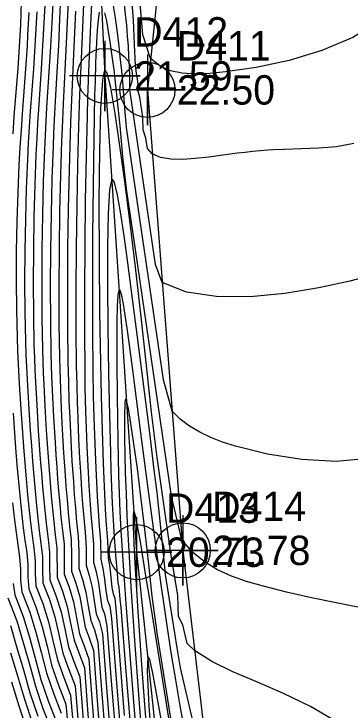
# Model space of a CAD drawing. Extents: x 2356077 to 2359823, y 225951 to 227822.
# Drawn here: x 2356540.3 to 2356568.9, y 227137.3 to 227196.5 of the extents above; entities that cross this region are included whole.
import ezdxf

# ---------------------------------------------------------------- set-up
doc = ezdxf.new("R2010")
doc.units = 0
for name, color, linetype in [('DTM Contours Major', 7, 'Continuous'), ('DTM Contours Minor', 7, 'Continuous'), ('Exist DTM Breakline', 7, 'Continuous'), ('Exist DTM Breakline Cogo Elevation', 7, 'Continuous'), ('Exist DTM Breakline Cogo Number', 7, 'Continuous'), ('Exist DTM Breakline Cogo Point CELL', 7, 'Continuous'), ('Exist DTM Drainline', 7, 'Continuous'), ('Exist DTM Drainline Cogo Elevation', 7, 'Continuous'), ('Exist DTM Drainline Cogo Number', 7, 'Continuous'), ('Exist DTM Drainline Cogo Point CELL', 7, 'Continuous')]:
    doc.layers.add(name, color=color, linetype=linetype)

msp = doc.modelspace()

# ---------------------------------------------------------------- linework, layer by layer
at = {"layer": 'DTM Contours Major'}
for points in [[(2356543.668, 227197.932), (2356543.555, 227195.776), (2356543.435, 227193.728), (2356543.102, 227188.52), (2356543.036, 227187.379), (2356542.973, 227186.181), (2356542.914, 227184.917), (2356542.816, 227182.253), (2356542.744, 227179.401), (2356542.698, 227176.454), (2356542.682, 227173.504), (2356542.698, 227170.646), (2356542.747, 227167.971), (2356542.779, 227166.924), (2356542.815, 227165.921), (2356542.857, 227164.957), (2356542.95, 227163.128), (2356543.071, 227161.068), (2356543.146, 227159.914), (2356543.225, 227158.787), (2356543.308, 227157.677), (2356543.397, 227156.58), (2356543.492, 227155.488), (2356543.594, 227154.39), (2356543.708, 227153.284), (2356543.837, 227152.165), (2356543.983, 227151.026), (2356543.989, 227148.575), (2356544.463, 227147.359), (2356544.86, 227146.052), (2356545.142, 227144.658), (2356545.433, 227143.196), (2356546.314, 227140.837), (2356546.579, 227137.306), (2356546.84, 227133.897)], [(2356546.929, 227197.348), (2356546.867, 227196.192), (2356546.806, 227194.951), (2356546.747, 227193.627), (2356546.662, 227191.54), (2356546.587, 227189.381), (2356546.54, 227187.827), (2356546.456, 227184.368), (2356546.388, 227180.637), (2356546.341, 227176.794), (2356546.315, 227173.003), (2356546.315, 227169.425), (2356546.341, 227166.221), (2356546.368, 227164.716), (2356546.419, 227162.698), (2356546.468, 227161.25), (2356546.531, 227159.692), (2356546.641, 227157.479), (2356546.706, 227156.322), (2356546.781, 227155.144), (2356546.869, 227153.938), (2356546.974, 227152.694), (2356547.097, 227151.397), (2356547.098, 227149.853), (2356547.307, 227149.016), (2356547.506, 227148.06), (2356547.649, 227146.995), (2356547.806, 227146.016), (2356548.034, 227145.43), (2356548.236, 227144.407), (2356548.56, 227140.088), (2356548.898, 227135.954)], [(2356570.489, 227158.651), (2356567.746, 227158.419), (2356564.825, 227158.57), (2356561.905, 227159.027), (2356559.169, 227159.71), (2356558.084, 227160.061), (2356557.07, 227160.452), (2356556.13, 227160.898), (2356555.266, 227161.411), (2356554.483, 227162.005), (2356553.783, 227162.691), (2356553.037, 227165.347), (2356550.876, 227180.208), (2356549.902, 227186.839), (2356549.751, 227188.487), (2356549.61, 227190.39), (2356549.497, 227191.653), (2356549.375, 227192.847), (2356549.243, 227193.998), (2356549.103, 227195.106), (2356548.957, 227196.169), (2356548.807, 227197.187)], [(2356553.962, 227134.786), (2356552.55, 227143.654), (2356552.093, 227146.937), (2356551.768, 227149.936), (2356551.435, 227152.861), (2356551.128, 227155.414), (2356550.825, 227157.797), (2356550.538, 227159.908), (2356550.28, 227161.646), (2356550.064, 227162.91), (2356549.902, 227163.599), (2356549.854, 227163.694), (2356549.816, 227163.686), (2356549.787, 227163.584), (2356549.765, 227163.397), (2356549.75, 227163.136), (2356549.735, 227162.513), (2356549.731, 227161.598), (2356549.74, 227160.407), (2356549.762, 227159.016), (2356549.801, 227157.439), (2356549.859, 227155.689), (2356549.937, 227153.781), (2356550.038, 227151.727), (2356550.147, 227149.8), (2356550.274, 227147.75), (2356550.581, 227143.176), (2356550.941, 227138.188), (2356551.339, 227132.961)], [(2356540.204, 227154.897), (2356540.369, 227153.404), (2356540.498, 227152.361), (2356540.639, 227151.324), (2356540.796, 227150.288), (2356540.87, 227149.255), (2356540.871, 227148.3), (2356540.987, 227147.327), (2356541.665, 227145.585), (2356542.191, 227143.883), (2356542.635, 227142.18), (2356543.086, 227140.417), (2356543.678, 227138.703), (2356544.347, 227136.985)], [(2356540.122, 227139.663), (2356540.749, 227137.606), (2356541.442, 227135.485)]]:
    msp.add_lwpolyline(points, dxfattribs=at)
at = {"layer": 'DTM Contours Minor'}
for points in [[(2356542.763, 227227.301), (2356542.028, 227218.472), (2356541.785, 227215.396), (2356541.559, 227212.326), (2356541.364, 227209.335), (2356541.213, 227206.5), (2356541.143, 227204.817), (2356541.091, 227203.219), (2356541.015, 227200.246), (2356540.981, 227198.855), (2356540.942, 227197.518), (2356540.906, 227196.553), (2356540.865, 227195.607), (2356540.818, 227194.67), (2356540.765, 227193.737), (2356540.706, 227192.799), (2356540.64, 227191.848), (2356540.434, 227189.167), (2356540.324, 227187.761), (2356540.216, 227186.305)], [(2356573.337, 227197.672), (2356571.477, 227195.905), (2356569.154, 227194.485), (2356566.522, 227193.377), (2356563.736, 227192.545), (2356560.95, 227191.952), (2356558.319, 227191.563), (2356556.988, 227191.429), (2356555.757, 227191.38), (2356554.633, 227191.448), (2356553.62, 227191.668), (2356552.726, 227192.072), (2356551.955, 227192.696), (2356551.295, 227194.728), (2356550.372, 227205.324)], [(2356546.386, 227200.636), (2356546.006, 227192.009), (2356545.909, 227189.6), (2356545.819, 227186.945), (2356545.734, 227183.703), (2356545.666, 227180.204), (2356545.618, 227176.592), (2356545.594, 227173.015), (2356545.596, 227169.617), (2356545.628, 227166.545), (2356545.661, 227164.926), (2356545.703, 227163.448), (2356545.752, 227162.086), (2356545.828, 227160.333), (2356545.913, 227158.69), (2356546.008, 227157.09), (2356546.082, 227155.952), (2356546.166, 227154.794), (2356546.263, 227153.608), (2356546.378, 227152.388), (2356546.474, 227151.073), (2356546.475, 227149.593), (2356546.733, 227148.698), (2356546.979, 227147.686), (2356547.147, 227146.55), (2356547.331, 227145.445), (2356547.6, 227144.754), (2356547.849, 227143.733), (2356548.163, 227139.539), (2356548.489, 227135.533)], [(2356544.997, 227198.977), (2356544.89, 227196.395), (2356544.776, 227194.013), (2356544.508, 227188.859), (2356544.414, 227186.807), (2356544.37, 227185.708), (2356544.278, 227182.812), (2356544.207, 227179.685), (2356544.159, 227176.446), (2356544.139, 227173.215), (2356544.148, 227170.109), (2356544.19, 227167.248), (2356544.213, 227166.306), (2356544.27, 227164.545), (2356544.339, 227162.922), (2356544.43, 227161.116), (2356544.547, 227159.141), (2356544.677, 227157.242), (2356544.747, 227156.299), (2356544.837, 227155.184), (2356544.937, 227154.054), (2356545.051, 227152.903), (2356545.184, 227151.726), (2356545.229, 227150.426), (2356545.23, 227149.076), (2356545.594, 227148.039), (2356545.921, 227146.889), (2356546.379, 227144.305), (2356546.732, 227143.4), (2356547.079, 227142.313), (2356547.37, 227138.428), (2356547.667, 227134.706)], [(2356569.24, 227185.465), (2356567.775, 227185.197), (2356566.265, 227185.067), (2356564.756, 227185.008), (2356563.328, 227184.96), (2356562.397, 227184.917), (2356561.937, 227184.889), (2356561.284, 227184.839), (2356560.637, 227184.78), (2356559.995, 227184.712), (2356559.358, 227184.637), (2356558.092, 227184.474), (2356556.899, 227184.314), (2356555.742, 227184.18), (2356554.654, 227184.106), (2356553.663, 227184.126), (2356552.802, 227184.275), (2356552.1, 227184.585), (2356551.675, 227185.038), (2356551.544, 227185.938), (2356551.313, 227186.636), (2356551.283, 227187.71), (2356551.032, 227189.427), (2356550.915, 227189.822), (2356550.859, 227189.988), (2356550.786, 227190.181), (2356550.896, 227190.515), (2356550.847, 227190.953), (2356550.753, 227191.468), (2356550.662, 227192.095), (2356550.621, 227193.302), (2356550.595, 227193.938), (2356550.485, 227195.977), (2356550.329, 227198.168)], [(2356542.978, 227197.74), (2356542.878, 227195.731), (2356542.765, 227193.776), (2356542.637, 227191.791), (2356542.408, 227188.405), (2356542.332, 227187.18), (2356542.26, 227185.896), (2356542.193, 227184.544), (2356542.093, 227181.969), (2356542.019, 227179.236), (2356541.973, 227176.426), (2356541.958, 227173.616), (2356541.975, 227170.885), (2356542.027, 227168.312), (2356542.062, 227167.22), (2356542.103, 227166.172), (2356542.15, 227165.162), (2356542.255, 227163.237), (2356542.392, 227161.05), (2356542.476, 227159.819), (2356542.564, 227158.612), (2356542.657, 227157.423), (2356542.757, 227156.247), (2356542.865, 227155.078), (2356542.973, 227153.989), (2356543.093, 227152.896), (2356543.229, 227151.793), (2356543.36, 227150.664), (2356543.361, 227149.488), (2356543.387, 227148.331), (2356543.9, 227147.014), (2356544.328, 227145.625), (2356544.641, 227144.17), (2356544.962, 227142.646), (2356545.428, 227141.374), (2356545.931, 227140.083), (2356546.426, 227133.498)], [(2356544.262, 227197.316), (2356544.211, 227196.086), (2356544.101, 227193.782), (2356543.98, 227191.563), (2356543.809, 227188.564), (2356543.698, 227186.38), (2356543.647, 227185.204), (2356543.552, 227182.448), (2356543.479, 227179.48), (2356543.432, 227176.406), (2356543.413, 227173.331), (2356543.425, 227170.361), (2356543.47, 227167.601), (2356543.497, 227166.607), (2356543.529, 227165.657), (2356543.603, 227163.868), (2356543.688, 227162.201), (2356543.817, 227160.016), (2356543.886, 227158.966), (2356543.959, 227157.936), (2356544.036, 227156.916), (2356544.119, 227155.898), (2356544.215, 227154.792), (2356544.322, 227153.674), (2356544.444, 227152.539), (2356544.585, 227151.381), (2356544.606, 227150.109), (2356544.607, 227148.823), (2356545.028, 227147.702), (2356545.391, 227146.474), (2356545.904, 227143.743), (2356546.298, 227142.724), (2356546.696, 227141.58), (2356546.974, 227137.868), (2356547.255, 227134.299)], [(2356569.882, 227174.016), (2356568.916, 227173.762), (2356566.283, 227173.181), (2356563.386, 227172.71), (2356560.415, 227172.434), (2356557.557, 227172.439), (2356555.003, 227172.812), (2356552.941, 227173.638), (2356552.36, 227175.167), (2356551.068, 227184.039), (2356550.24, 227189.68), (2356550.212, 227189.848), (2356550.184, 227190.055), (2356550.174, 227191.151), (2356550.152, 227192.016), (2356550.114, 227192.884), (2356550.061, 227193.759), (2356549.996, 227194.647), (2356549.917, 227195.551), (2356549.826, 227196.477), (2356549.673, 227197.875)], [(2356541.581, 227196.628), (2356541.537, 227195.664), (2356541.487, 227194.711), (2356541.432, 227193.761), (2356541.305, 227191.838), (2356541.019, 227187.984), (2356540.922, 227186.603), (2356540.829, 227185.165), (2356540.745, 227183.664), (2356540.641, 227181.294), (2356540.566, 227178.822), (2356540.521, 227176.3), (2356540.508, 227173.783), (2356540.528, 227171.322), (2356540.582, 227168.972), (2356540.625, 227167.806), (2356540.676, 227166.679), (2356540.734, 227165.586), (2356540.797, 227164.521), (2356540.933, 227162.451), (2356541.134, 227159.648), (2356541.241, 227158.275), (2356541.356, 227156.919), (2356541.48, 227155.578), (2356541.615, 227154.25), (2356541.734, 227153.181), (2356541.865, 227152.114), (2356542.012, 227151.043), (2356542.115, 227149.952), (2356542.116, 227148.887), (2356542.184, 227147.835), (2356542.779, 227146.31), (2356543.261, 227144.759), (2356543.638, 227143.181), (2356544.023, 227141.536), (2356544.555, 227140.033), (2356545.142, 227138.527), (2356545.392, 227135.607)], [(2356542.255, 227196.685), (2356542.207, 227195.706), (2356542.099, 227193.776), (2356541.971, 227191.821), (2356541.714, 227188.2), (2356541.627, 227186.897), (2356541.545, 227185.534), (2356541.47, 227184.104), (2356541.367, 227181.631), (2356541.292, 227179.029), (2356541.247, 227176.363), (2356541.233, 227173.7), (2356541.251, 227171.105), (2356541.305, 227168.643), (2356541.344, 227167.512), (2356541.39, 227166.423), (2356541.442, 227165.371), (2356541.559, 227163.353), (2356541.712, 227161.042), (2356541.805, 227159.731), (2356541.903, 227158.443), (2356542.007, 227157.171), (2356542.118, 227155.914), (2356542.239, 227154.666), (2356542.353, 227153.587), (2356542.479, 227152.506), (2356542.621, 227151.419), (2356542.738, 227150.306), (2356542.738, 227149.185), (2356542.785, 227148.085), (2356543.338, 227146.664), (2356543.795, 227145.194), (2356544.139, 227143.677), (2356544.493, 227142.092), (2356544.992, 227140.702), (2356545.537, 227139.304), (2356545.787, 227136.175)], [(2356545.549, 227196.719), (2356545.388, 227193.065), (2356545.212, 227189.2), (2356545.136, 227187.293), (2356545.1, 227186.277), (2356545.011, 227183.222), (2356544.941, 227179.921), (2356544.893, 227176.505), (2356544.87, 227173.107), (2356544.875, 227169.86), (2356544.911, 227166.896), (2356544.952, 227165.162), (2356545.004, 227163.577), (2356545.065, 227162.114), (2356545.158, 227160.221), (2356545.261, 227158.438), (2356545.377, 227156.696), (2356545.459, 227155.571), (2356545.551, 227154.428), (2356545.657, 227153.261), (2356545.781, 227152.063), (2356545.851, 227150.748), (2356545.852, 227149.333), (2356546.162, 227148.372), (2356546.45, 227147.294), (2356546.646, 227146.09), (2356546.855, 227144.875), (2356547.166, 227144.077), (2356547.463, 227143.033), (2356547.766, 227138.985), (2356548.079, 227135.117)], [(2356547.569, 227196.652), (2356547.485, 227195.995), (2356547.412, 227195.119), (2356547.349, 227194.052), (2356547.274, 227192.324), (2356547.222, 227190.728), (2356547.191, 227189.575), (2356547.113, 227185.895), (2356547.055, 227181.853), (2356547.018, 227177.651), (2356547.003, 227173.488), (2356547.01, 227169.565), (2356547.042, 227166.082), (2356547.077, 227163.983), (2356547.122, 227162.144), (2356547.194, 227159.896), (2356547.277, 227157.848), (2356547.334, 227156.65), (2356547.399, 227155.441), (2356547.477, 227154.208), (2356547.571, 227152.937), (2356547.685, 227151.618), (2356547.72, 227150.085), (2356547.893, 227149.302), (2356548.035, 227148.387), (2356548.153, 227147.402), (2356548.283, 227146.584), (2356548.47, 227146.103), (2356548.627, 227145.035), (2356548.957, 227140.627), (2356549.306, 227136.379)], [(2356571.57, 227145.602), (2356567.735, 227146.367), (2356565.641, 227146.807), (2356563.522, 227147.289), (2356561.446, 227147.816), (2356560.114, 227148.202), (2356558.843, 227148.647), (2356557.647, 227149.187), (2356556.538, 227149.859), (2356555.526, 227150.7), (2356554.624, 227151.747), (2356553.724, 227155.47), (2356550.673, 227176.446), (2356549.914, 227181.614), (2356549.589, 227184.375), (2356549.356, 227186.963), (2356549.115, 227189.35), (2356548.842, 227191.727), (2356548.717, 227192.706), (2356548.547, 227193.93), (2356548.378, 227195.01), (2356548.214, 227195.912), (2356548.057, 227196.602)], [(2356567.834, 227136.218), (2356565.576, 227137.551), (2356563.278, 227138.665), (2356561.04, 227139.629), (2356558.964, 227140.512), (2356557.151, 227141.385), (2356555.702, 227142.316), (2356555.069, 227142.92), (2356554.703, 227144.513), (2356554.322, 227145.221), (2356554.288, 227146.102), (2356554.261, 227146.992), (2356553.684, 227150.616), (2356552.501, 227158.737), (2356552.018, 227162.597), (2356551.597, 227166.583), (2356551.14, 227170.724), (2356550.656, 227174.942), (2356550.213, 227178.681), (2356549.77, 227182.248), (2356549.347, 227185.271), (2356548.941, 227188.03), (2356548.575, 227190.228), (2356548.265, 227191.415), (2356548.223, 227191.51), (2356548.183, 227191.581), (2356548.145, 227191.627), (2356548.108, 227191.648), (2356548.072, 227191.644), (2356548.038, 227191.614), (2356548.005, 227191.554), (2356547.973, 227191.466), (2356547.943, 227191.351), (2356547.914, 227191.208), (2356547.886, 227191.04), (2356547.86, 227190.846), (2356547.693, 227188.462), (2356547.597, 227184.892), (2356547.56, 227180.538), (2356547.569, 227175.808), (2356547.613, 227171.104), (2356547.68, 227166.831), (2356547.743, 227163.936), (2356547.822, 227161.063), (2356547.915, 227158.267), (2356547.967, 227156.927), (2356548.025, 227155.62), (2356548.093, 227154.322), (2356548.175, 227153.009), (2356548.277, 227151.659), (2356548.343, 227150.181), (2356548.482, 227149.427), (2356548.663, 227147.686), (2356548.763, 227147.143), (2356548.909, 227146.767), (2356549.026, 227145.558), (2356549.358, 227141.119), (2356549.714, 227136.785)], [(2356556.022, 227134.262), (2356554.51, 227140.858), (2356554.22, 227142.558), (2356553.226, 227148.799), (2356553.094, 227149.999), (2356552.908, 227151.956), (2356552.711, 227153.862), (2356552.498, 227155.772), (2356552.268, 227157.706), (2356551.875, 227160.844), (2356550.833, 227168.997), (2356550.325, 227172.911), (2356550.006, 227175.319), (2356549.689, 227177.617), (2356549.383, 227179.643), (2356549.099, 227181.233), (2356548.849, 227182.225), (2356548.642, 227182.456), (2356548.458, 227181.539), (2356548.345, 227179.507), (2356548.292, 227176.673), (2356548.286, 227173.355), (2356548.314, 227169.866), (2356548.375, 227165.904), (2356548.452, 227162.357), (2356548.536, 227159.15), (2356548.581, 227157.666), (2356548.631, 227156.234), (2356548.69, 227154.824), (2356548.763, 227153.408), (2356548.853, 227151.957), (2356548.965, 227150.441), (2356549.096, 227148.901), (2356549.168, 227148.089), (2356549.237, 227147.716), (2356549.332, 227146.683), (2356549.431, 227145.992), (2356549.76, 227141.596), (2356551.67, 227118.423)], [(2356554.944, 227134.978), (2356554.47, 227137.607), (2356554.093, 227139.832), (2356553.745, 227141.98), (2356553.426, 227144.045), (2356553.132, 227146.02), (2356552.861, 227147.899), (2356552.359, 227151.51), (2356551.74, 227156.12), (2356551.121, 227160.854), (2356550.408, 227166.416), (2356550.127, 227168.535), (2356549.959, 227169.75), (2356549.796, 227170.86), (2356549.642, 227171.804), (2356549.5, 227172.521), (2356549.376, 227172.949), (2356549.272, 227173.027), (2356549.177, 227172.583), (2356549.114, 227171.622), (2356549.08, 227170.265), (2356549.068, 227168.631), (2356549.073, 227166.843), (2356549.103, 227163.961), (2356549.164, 227160.235), (2356549.194, 227158.724), (2356549.231, 227157.224), (2356549.279, 227155.709), (2356549.34, 227154.157), (2356549.418, 227152.543), (2356549.519, 227150.845), (2356549.669, 227148.69), (2356549.849, 227146.315), (2356550.531, 227137.597), (2356550.923, 227132.694)], [(2356540.244, 227162.532), (2356540.462, 227159.568), (2356540.58, 227158.109), (2356540.705, 227156.666), (2356540.842, 227155.239), (2356540.991, 227153.83), (2356541.115, 227152.773), (2356541.252, 227151.72), (2356541.404, 227150.666), (2356541.493, 227149.602), (2356541.493, 227148.592), (2356541.585, 227147.583), (2356542.221, 227145.95), (2356542.726, 227144.322), (2356543.137, 227142.681), (2356543.555, 227140.977), (2356544.117, 227139.366), (2356544.745, 227137.754), (2356544.997, 227135.037)], [(2356553.609, 227135.858), (2356551.992, 227145.997), (2356551.532, 227148.854), (2356551.139, 227151.237), (2356550.998, 227152.063), (2356550.872, 227152.771), (2356550.762, 227153.348), (2356550.668, 227153.781), (2356550.592, 227154.059), (2356550.532, 227154.168), (2356550.491, 227154.098), (2356550.467, 227153.855), (2356550.459, 227153.446), (2356550.468, 227152.883), (2356550.491, 227152.174), (2356550.552, 227150.828), (2356550.612, 227149.721), (2356550.867, 227145.659), (2356551.214, 227140.695), (2356551.628, 227135.125)], [(2356540.248, 227148.011), (2356540.39, 227147.067), (2356541.112, 227145.214), (2356541.654, 227143.442), (2356542.133, 227141.676), (2356542.618, 227139.855), (2356543.236, 227138.044), (2356543.947, 227136.22)], [(2356539.795, 227146.804), (2356540.562, 227144.835), (2356541.117, 227143.002), (2356541.631, 227141.172), (2356542.151, 227139.292), (2356542.793, 227137.392), (2356543.545, 227135.462)], [(2356540.014, 227144.45), (2356540.578, 227142.562), (2356541.128, 227140.668), (2356541.684, 227138.729), (2356542.347, 227136.746)], [(2356540.038, 227142.125), (2356540.625, 227140.164), (2356541.216, 227138.167), (2356541.897, 227136.11)], [(2356552.9, 227136.17), (2356552.495, 227138.528), (2356552.146, 227140.388), (2356551.875, 227141.551), (2356551.705, 227141.822), (2356551.66, 227140.558), (2356551.812, 227137.584), (2356552.483, 227128.619)]]:
    msp.add_lwpolyline(points, dxfattribs=at)
at = {"layer": 'Exist DTM Breakline'}
msp.add_lwpolyline([(2356554.802, 227220.421), (2356551.682, 227190.031), (2356554.693, 227150.844), (2356559.046, 227114.057), (2356563.68, 227075.466), (2356576.505, 227009.716)], dxfattribs=at)
at = {"layer": 'Exist DTM Breakline Cogo Point CELL'}
for points in [[(2356551.682, 227193.031), (2356551.682, 227187.031), (2356551.682, 227190.031), (2356554.682, 227190.031), (2356548.682, 227190.031)], [(2356554.693, 227153.844), (2356554.693, 227147.844), (2356554.693, 227150.844), (2356557.693, 227150.844), (2356551.693, 227150.844)]]:
    msp.add_lwpolyline(points, dxfattribs=at)
for centre in [(2356551.682, 227190.031), (2356554.693, 227150.844)]:
    msp.add_circle(centre, 2.344, dxfattribs=at)
at = {"layer": 'Exist DTM Drainline'}
msp.add_lwpolyline([(2356548.776, 227304.309), (2356547.572, 227273.186), (2356546.306, 227228.878), (2356548.057, 227191.22), (2356550.765, 227150.688), (2356554.732, 227113.271), (2356560.954, 227074.926), (2356573.805, 227008.735)], dxfattribs=at)
at = {"layer": 'Exist DTM Drainline Cogo Point CELL'}
for points in [[(2356548.057, 227194.22), (2356548.057, 227188.22), (2356548.057, 227191.22), (2356551.057, 227191.22), (2356545.057, 227191.22)], [(2356550.765, 227153.688), (2356550.765, 227147.688), (2356550.765, 227150.688), (2356553.765, 227150.688), (2356547.765, 227150.688)]]:
    msp.add_lwpolyline(points, dxfattribs=at)
for centre in [(2356548.057, 227191.22), (2356550.765, 227150.688)]:
    msp.add_circle(centre, 2.344, dxfattribs=at)

# ---------------------------------------------------------------- texts
at = {"layer": 'Exist DTM Breakline Cogo Elevation'}
for s, p in [('22.50', (2356554.182, 227188.781)), ('21.78', (2356557.193, 227149.594))]:
    msp.add_text(s, height=2.5, dxfattribs=at).set_placement(p)
at = {"layer": 'Exist DTM Breakline Cogo Number'}
for s, p in [('D411', (2356554.182, 227192.531)), ('D414', (2356557.193, 227153.344))]:
    msp.add_text(s, height=2.5, dxfattribs=at).set_placement(p)
at = {"layer": 'Exist DTM Drainline Cogo Elevation'}
for s, p in [('21.59', (2356550.557, 227189.97)), ('20.73', (2356553.265, 227149.438))]:
    msp.add_text(s, height=2.5, dxfattribs=at).set_placement(p)
at = {"layer": 'Exist DTM Drainline Cogo Number'}
for s, p in [('D412', (2356550.557, 227193.72)), ('D413', (2356553.265, 227153.188))]:
    msp.add_text(s, height=2.5, dxfattribs=at).set_placement(p)

doc.saveas('drawing.dxf')
